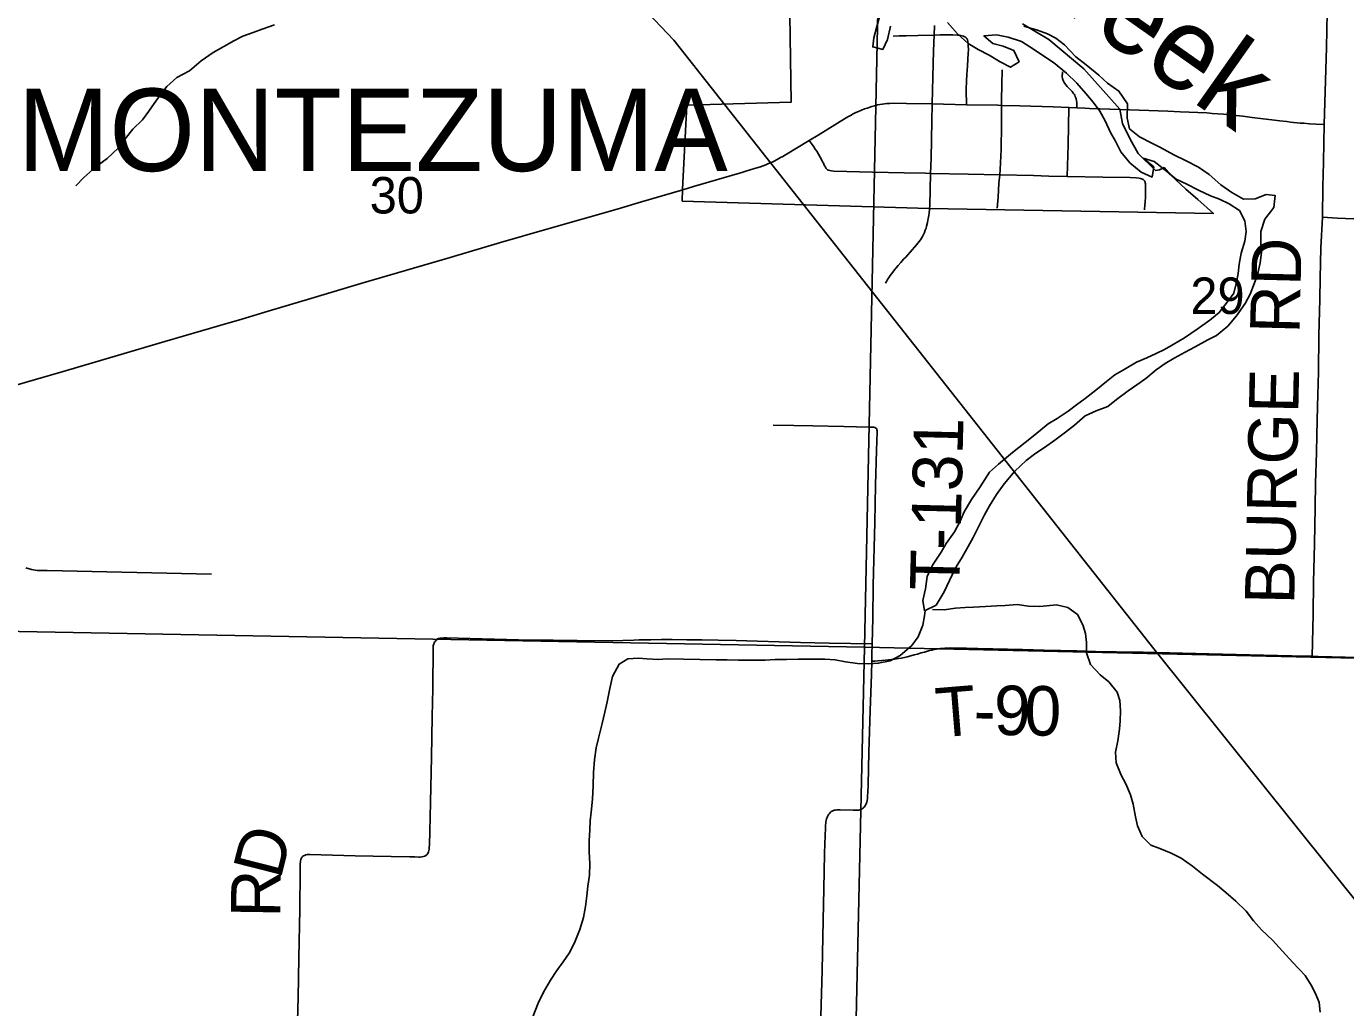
# Model space of a CAD drawing. Extents: x -38.1 to 35.9, y -2.7 to 28.5.
# Drawn here: x 22.099 to 23.615, y 15.586 to 16.713 of the extents above; entities that cross this region are included whole.
import ezdxf

# ---------------------------------------------------------------- set-up
doc = ezdxf.new("R2010")
doc.units = 0
for name, color, linetype in [('GM_X_City_Street', 7, 'Continuous'), ('GM_X_City_Street_Text', 7, 'Continuous'), ('GM_X_Corporation', 7, 'Continuous'), ('GM_X_Interchange_Ramps', 7, 'Continuous'), ('GM_X_Interstate_Shield', 7, 'Continuous'), ('GM_X_Major_River_Text', 7, 'Continuous'), ('GM_X_Minor_Lake', 7, 'Continuous'), ('GM_X_Minor_River', 7, 'Continuous'), ('GM_X_Section', 7, 'Continuous'), ('GM_X_Township_Road_Text', 7, 'Continuous'), ('GM_X_Township_Subdivision', 7, 'Continuous'), ('GM_X_US_Route', 7, 'Continuous')]:
    doc.layers.add(name, color=color, linetype=linetype)

msp = doc.modelspace()

# ---------------------------------------------------------------- linework, layer by layer
at = {"layer": 'GM_X_City_Street'}
for points in [[(23.0952, 16.7014), (23.1018, 16.7016), (23.1101, 16.7017), (23.1234, 16.7021), (23.1421, 16.7025), (23.149, 16.7027), (23.1593, 16.7028), (23.1635, 16.7027), (23.1691, 16.7025), (23.1712, 16.7023), (23.1728, 16.702), (23.1744, 16.7016), (23.1758, 16.7012), (23.1772, 16.7005), (23.1785, 16.6997), (23.1795, 16.6986), (23.1803, 16.6972), (23.1808, 16.6954), (23.1811, 16.693), (23.1813, 16.6904), (23.1814, 16.6862), (23.1813, 16.6814), (23.1809, 16.6751), (23.1803, 16.667), (23.1799, 16.6621), (23.1795, 16.6571), (23.1792, 16.6505), (23.1789, 16.6397), (23.1792, 16.6226)], [(23.2193, 16.6218), (23.2195, 16.6277), (23.22, 16.646), (23.2204, 16.6628)], [(23.3062, 16.619), (23.3062, 16.6229), (23.3061, 16.6252), (23.3058, 16.627), (23.3054, 16.6292), (23.3049, 16.6306), (23.3043, 16.632), (23.3036, 16.6334), (23.3028, 16.6346), (23.3019, 16.636), (23.3007, 16.6376), (23.2991, 16.6394), (23.2969, 16.6417), (23.2951, 16.6435), (23.2934, 16.6454), (23.2922, 16.6469), (23.2914, 16.6482), (23.2906, 16.6498), (23.2899, 16.6517), (23.2895, 16.6529), (23.2893, 16.6543), (23.2892, 16.6556), (23.2892, 16.6569), (23.2894, 16.6582), (23.2897, 16.6602)], [(23.2147, 16.5039), (23.2155, 16.5166), (23.2165, 16.5324), (23.2175, 16.542), (23.2178, 16.5482), (23.219, 16.571), (23.2193, 16.5994), (23.2193, 16.6218)], [(23.2951, 16.54), (23.2959, 16.5768), (23.2967, 16.6193)], [(22.9984, 16.5814), (23.0018, 16.5769), (23.0037, 16.5743), (23.0056, 16.5717), (23.0072, 16.5691), (23.0091, 16.566), (23.0111, 16.5625), (23.0126, 16.5596), (23.014, 16.5569), (23.0148, 16.5554), (23.0154, 16.5543), (23.0163, 16.5526), (23.0173, 16.5508), (23.0182, 16.5494), (23.0194, 16.548), (23.0207, 16.5473), (23.0223, 16.5469), (23.0242, 16.5466), (23.0268, 16.5463), (23.0712, 16.5452), (23.1078, 16.5444), (23.132, 16.5439), (23.138, 16.5437)], [(23.138, 16.5437), (23.1812, 16.543), (23.2175, 16.542), (23.2562, 16.5413), (23.2739, 16.5407), (23.2951, 16.54), (23.3358, 16.5394), (23.3674, 16.5389), (23.3743, 16.5386), (23.3778, 16.5382), (23.3792, 16.5379), (23.3805, 16.5376), (23.3815, 16.5371), (23.3822, 16.5366), (23.3831, 16.536), (23.3837, 16.5353), (23.3842, 16.5345), (23.3845, 16.5338), (23.3847, 16.5329), (23.3849, 16.5318), (23.3849, 16.5307), (23.385, 16.5293), (23.3851, 16.5277), (23.3851, 16.5253), (23.3851, 16.5209), (23.385, 16.5178), (23.3849, 16.5154), (23.3847, 16.5124), (23.3844, 16.51), (23.3843, 16.508), (23.3836, 16.502)]]:
    msp.add_lwpolyline(points, dxfattribs=at)
at = {"layer": 'GM_X_City_Street_Text'}
for points in [[(23.5902, 16.5999), (23.5898, 16.5791), (23.5894, 16.5561), (23.5887, 16.5287), (23.5881, 16.4933)], [(23.5881, 16.4933), (23.6057, 16.4923), (23.6149, 16.4919), (23.6242, 16.4916), (23.659, 16.491), (23.756, 16.489), (23.7901, 16.488), (23.8311, 16.4871), (23.9206, 16.4851), (24.0001, 16.4833), (24.0324, 16.4826), (24.0907, 16.4813)]]:
    msp.add_lwpolyline(points, dxfattribs=at)
at = {"layer": 'GM_X_Corporation'}
msp.add_lwpolyline([(25.4101, 13.4873), (25.0847, 13.9186), (24.5478, 14.5412), (23.9622, 15.2897), (23.3945, 15.9977), (22.8429, 16.6968), (22.7771, 16.7664), (22.2793, 17.0387), (22.174, 17.095), (22.1183, 17.1348), (22.0806, 17.1798), (21.9636, 17.4041), (21.7841, 17.7749), (21.744, 17.8537), (21.7155, 17.9287), (21.6978, 17.9866), (21.6921, 18.0413), (21.6956, 18.1468), (21.7163, 18.7934), (21.7602, 19.7303), (21.7602, 19.7308)], dxfattribs=at)
at = {"layer": 'GM_X_Interchange_Ramps'}
for points in [[(23.5902, 16.5999), (23.5928, 16.6884), (23.5935, 16.7282)], [(23.1399, 16.6235), (23.1411, 16.6695), (23.1415, 16.6844), (23.1421, 16.7025), (23.1424, 16.7135)], [(22.9211, 16.5448), (22.9259, 16.5462), (22.9357, 16.5493), (22.9425, 16.5514), (22.9456, 16.5525), (22.9488, 16.5537), (22.9517, 16.5549), (22.9551, 16.5564), (22.9582, 16.5579), (22.9617, 16.5597), (22.9655, 16.5618), (22.9683, 16.5633), (22.9714, 16.5652), (22.9984, 16.5814), (23.0087, 16.5876), (23.0392, 16.6063), (23.043, 16.6086), (23.0461, 16.6104), (23.049, 16.612), (23.052, 16.6135), (23.0552, 16.6149), (23.0585, 16.6164), (23.0619, 16.6177), (23.0652, 16.6188), (23.0705, 16.6205), (23.0737, 16.6214), (23.0772, 16.6223), (23.0798, 16.6229), (23.0827, 16.6234), (23.0851, 16.6237), (23.0877, 16.624), (23.0912, 16.6241), (23.0953, 16.6242), (23.1102, 16.6239), (23.1399, 16.6235)], [(23.1399, 16.6235), (23.1792, 16.6226), (23.2153, 16.6219)], [(23.2153, 16.6219), (23.2193, 16.6218), (23.2405, 16.6214), (23.2789, 16.62), (23.2967, 16.6193), (23.3062, 16.619), (23.3154, 16.6186)], [(23.3154, 16.6186), (23.3205, 16.6184), (23.3559, 16.617)], [(23.3559, 16.617), (23.4107, 16.6153), (23.4249, 16.6146)], [(23.4249, 16.6146), (23.4554, 16.6132), (23.4614, 16.6127), (23.4681, 16.6121), (23.4745, 16.6116), (23.481, 16.6109), (23.489, 16.6101), (23.4969, 16.6093), (23.5076, 16.6081), (23.5203, 16.6065), (23.53, 16.6054), (23.5393, 16.6042), (23.5475, 16.6032), (23.5514, 16.6027), (23.5551, 16.6023), (23.5592, 16.6019), (23.5627, 16.6016), (23.5667, 16.6013), (23.5734, 16.6008), (23.581, 16.6004), (23.5902, 16.5999)], [(22.8533, 16.525), (22.8657, 16.5286), (22.9211, 16.5448)], [(21.976, 16.2689), (21.9979, 16.2748), (22.022, 16.2818), (22.0591, 16.2924), (22.0859, 16.3002), (22.1098, 16.307), (22.1414, 16.3163), (22.2011, 16.3337), (22.2583, 16.3506), (22.3215, 16.3692), (22.3466, 16.3764), (22.3769, 16.3856), (22.4258, 16.4), (22.4836, 16.4171), (22.5862, 16.4472), (22.644, 16.4643), (22.6972, 16.4795), (22.7778, 16.5028), (22.8058, 16.5111), (22.8533, 16.525)]]:
    msp.add_lwpolyline(points, dxfattribs=at)
at = {"layer": 'GM_X_Interstate_Shield'}
for points in [[(23.0797, 16.7245), (23.0763, 16.7124), (23.073, 16.6996), (23.0716, 16.689), (23.083, 16.6861), (23.0885, 16.6974), (23.0919, 16.7129)], [(23.2959, 16.2708), (23.2836, 16.2624), (23.2732, 16.2562), (23.2577, 16.2436), (23.2465, 16.2348), (23.2322, 16.2233), (23.2159, 16.2096), (23.2058, 16.2004), (23.1948, 16.1839), (23.185, 16.1693), (23.1767, 16.1551), (23.1719, 16.1442), (23.1656, 16.1322), (23.1561, 16.1187), (23.1502, 16.1086), (23.1404, 16.0936), (23.134, 16.0809), (23.1322, 16.0665), (23.1292, 16.0533), (23.1312, 16.0414), (23.1443, 16.048), (23.1538, 16.063), (23.1597, 16.0761), (23.1673, 16.0919), (23.1744, 16.1031), (23.1811, 16.1151), (23.1871, 16.1256), (23.1922, 16.1361), (23.1998, 16.1515), (23.2057, 16.162), (23.2136, 16.1751), (23.2226, 16.1871), (23.2347, 16.2016), (23.2479, 16.2138), (23.2588, 16.2223), (23.2688, 16.2289), (23.2807, 16.2374), (23.2931, 16.2466), (23.3032, 16.2547), (23.3156, 16.2651), (23.3282, 16.2709), (23.3416, 16.2759), (23.3517, 16.284), (23.3652, 16.294), (23.3749, 16.3009), (23.3853, 16.3083), (23.3973, 16.3183), (23.4077, 16.3253), (23.4177, 16.3315), (23.4304, 16.3384), (23.4419, 16.3446), (23.4566, 16.3526), (23.4666, 16.3577), (23.4797, 16.3684), (23.4895, 16.38), (23.4993, 16.3942), (23.5052, 16.405), (23.5109, 16.4201), (23.5145, 16.4307), (23.5167, 16.4409), (23.5181, 16.453), (23.5176, 16.4636), (23.5175, 16.4769), (23.522, 16.4912), (23.5325, 16.5047), (23.534, 16.5183), (23.5237, 16.5193), (23.5111, 16.5146), (23.4974, 16.5142), (23.4843, 16.5217), (23.4716, 16.5307), (23.4582, 16.5424), (23.4458, 16.5507), (23.4308, 16.5586), (23.4176, 16.565), (23.4022, 16.5733), (23.3921, 16.5785), (23.3782, 16.5856), (23.3666, 16.595), (23.3639, 16.6072), (23.3642, 16.6235), (23.3543, 16.6382), (23.3412, 16.6472), (23.3312, 16.6566), (23.3166, 16.6683), (23.305, 16.6777), (23.292, 16.6912), (23.282, 16.6991), (23.2722, 16.7042), (23.2609, 16.7083), (23.245, 16.7128)], [(23.1574, 16.7171), (23.1689, 16.7039), (23.1811, 16.693), (23.1928, 16.6859), (23.2055, 16.6795), (23.2179, 16.672), (23.2299, 16.6657), (23.2396, 16.6719), (23.2338, 16.685), (23.2213, 16.6898), (23.2096, 16.6931), (23.1992, 16.7017), (23.2137, 16.7029), (23.2273, 16.7003), (23.2424, 16.6954), (23.2562, 16.6864), (23.2693, 16.6777), (23.2794, 16.671), (23.294, 16.6589), (23.3059, 16.6473), (23.3163, 16.6356), (23.3248, 16.6256), (23.3325, 16.6151), (23.3387, 16.604), (23.3449, 16.5906), (23.3504, 16.5806), (23.3565, 16.5683), (23.3669, 16.5559), (23.38, 16.5453), (23.3924, 16.5394), (23.3945, 16.5511), (23.3822, 16.5612), (23.3947, 16.5575), (23.407, 16.5478), (23.42, 16.5372), (23.4324, 16.5312), (23.446, 16.5245), (23.4595, 16.5181), (23.4701, 16.5141), (23.481, 16.5089), (23.4929, 16.501), (23.4991, 16.4891), (23.5004, 16.4769), (23.499, 16.4659), (23.4949, 16.452), (23.4927, 16.4395), (23.4913, 16.4289), (23.4896, 16.4187), (23.4863, 16.4062), (23.4788, 16.3958), (23.4694, 16.3838), (23.459, 16.375), (23.4443, 16.3647), (23.4296, 16.3548), (23.4169, 16.3471), (23.4069, 16.3416), (23.3973, 16.3369), (23.3866, 16.3318), (23.3747, 16.3268), (23.3604, 16.3184), (23.3497, 16.3122), (23.34, 16.3048), (23.328, 16.2948), (23.3156, 16.2852), (23.3056, 16.2778), (23.2959, 16.2708)]]:
    msp.add_lwpolyline(points, dxfattribs=at)
at = {"layer": 'GM_X_Major_River_Text'}
for points in [[(23.138, 16.5437), (23.1386, 16.5614), (23.1395, 16.6039), (23.1399, 16.6235)], [(23.1368, 16.5029), (23.1371, 16.5068), (23.1374, 16.5247), (23.138, 16.5437)], [(23.0863, 16.4178), (23.0874, 16.4197), (23.0882, 16.4212), (23.0892, 16.4229), (23.0905, 16.4247), (23.0916, 16.4264), (23.0931, 16.4285), (23.0945, 16.4302), (23.0965, 16.4328), (23.0984, 16.4352), (23.1007, 16.438), (23.1038, 16.4415), (23.107, 16.4451), (23.1094, 16.4476), (23.1117, 16.4501), (23.1145, 16.4531), (23.117, 16.456), (23.1195, 16.4589), (23.1219, 16.4617), (23.1235, 16.4636), (23.125, 16.4656), (23.1264, 16.4675), (23.1275, 16.4693), (23.1287, 16.4712), (23.1297, 16.4734), (23.1309, 16.4758), (23.1319, 16.4784), (23.1328, 16.4809), (23.1334, 16.4832), (23.1345, 16.4874), (23.1354, 16.492), (23.136, 16.4955), (23.1363, 16.4983), (23.1367, 16.5017), (23.1368, 16.5029)], [(23.5766, 15.9891), (23.5774, 16.0372), (23.578, 16.0742), (23.5791, 16.1183), (23.5799, 16.1599), (23.5804, 16.1879), (23.5813, 16.2233), (23.5819, 16.2432), (23.5825, 16.2761), (23.5836, 16.3159), (23.5842, 16.3575), (23.5852, 16.3991), (23.5857, 16.4234), (23.5865, 16.4581), (23.5881, 16.4933)], [(22.957, 16.2546), (22.9809, 16.2542), (23.0028, 16.2539), (23.0382, 16.253), (23.0673, 16.2523), (23.071, 16.2523), (23.0728, 16.2522), (23.0741, 16.2518), (23.075, 16.2513), (23.0757, 16.2507)], [(23.0708, 16.0035), (23.0715, 16.0328), (23.0721, 16.0708), (23.0738, 16.1428), (23.0746, 16.1857), (23.0759, 16.2255), (23.0766, 16.2469), (23.0765, 16.2482), (23.0764, 16.2491), (23.0761, 16.25), (23.0757, 16.2507)], [(22.0986, 16.0907), (22.105, 16.0887), (22.1114, 16.0877), (22.123, 16.0875), (22.3117, 16.0836)], [(22.4105, 15.5699), (22.4113, 15.5973), (22.4122, 15.6429), (22.4133, 15.6986), (22.4139, 15.7415), (22.4138, 15.7489), (22.4138, 15.7511), (22.414, 15.7529), (22.4141, 15.7543), (22.4145, 15.7556), (22.4148, 15.7564), (22.4153, 15.7575), (22.4159, 15.7585), (22.4166, 15.7593), (22.4174, 15.7599), (22.4187, 15.7605), (22.4201, 15.761), (22.4218, 15.7613), (22.4232, 15.7614), (22.4251, 15.7614), (22.438, 15.7611), (22.4769, 15.7601), (22.5183, 15.7591), (22.5398, 15.7588), (22.5455, 15.7586), (22.5499, 15.7585), (22.5517, 15.7585), (22.5535, 15.7586), (22.5554, 15.759), (22.5571, 15.7596), (22.5586, 15.7606), (22.5595, 15.7614), (22.5601, 15.7624), (22.5607, 15.7633), (22.5612, 15.7647), (22.5616, 15.7662), (22.5619, 15.7677), (22.562, 15.7699), (22.5623, 15.7727), (22.5627, 15.7883), (22.5631, 15.8044), (22.5646, 15.8731), (22.5655, 15.92), (22.5661, 15.9523), (22.5662, 15.9629), (22.5663, 15.9685), (22.5664, 15.9827), (22.5664, 15.9944), (22.5664, 15.9965), (22.5665, 15.9992), (22.5667, 16.001), (22.567, 16.0022), (22.5673, 16.0033), (22.5677, 16.0043), (22.5681, 16.0052), (22.5687, 16.006), (22.5695, 16.0071), (22.5703, 16.0078), (22.5709, 16.0085), (22.5717, 16.0091), (22.5725, 16.0094), (22.5733, 16.0097), (22.5745, 16.0099), (22.5763, 16.0101), (22.5786, 16.0102), (22.5823, 16.0103), (22.5952, 16.0099), (22.6647, 16.0082), (22.7044, 16.0075), (22.72, 16.0073)], [(22.72, 16.0073), (22.7318, 16.0071), (22.7726, 16.007), (22.7843, 16.0073), (22.7969, 16.0078), (22.8033, 16.008), (22.81, 16.0082), (22.8167, 16.0082), (22.8287, 16.0083), (22.8411, 16.0084), (22.8579, 16.0082), (22.8753, 16.008), (22.8941, 16.0076), (22.9148, 16.0071), (22.9884, 16.0051), (23.0214, 16.0043), (23.0708, 16.0035)], [(23.0704, 15.9834), (23.0705, 15.9912), (23.0708, 16.0035)], [(23.0704, 15.9834), (23.0741, 15.9835), (23.0774, 15.9837), (23.082, 15.9841), (23.0861, 15.9845), (23.0896, 15.985), (23.0933, 15.9855), (23.097, 15.9859), (23.1008, 15.9865), (23.1043, 15.9871), (23.1081, 15.9878), (23.1112, 15.9886), (23.1152, 15.9896), (23.119, 15.9906), (23.1231, 15.9917), (23.1273, 15.993), (23.131, 15.994), (23.1343, 15.9949), (23.1369, 15.9956), (23.1393, 15.9962), (23.142, 15.9968), (23.1448, 15.9973), (23.1469, 15.9976), (23.1492, 15.9979), (23.1515, 15.9982), (23.1542, 15.9984), (23.1579, 15.9986), (23.1608, 15.9987), (23.1668, 15.9986), (23.1792, 15.9983), (23.1924, 15.9979), (23.2438, 15.9969), (23.2686, 15.9963), (23.3059, 15.9953), (23.3273, 15.9948), (23.3514, 15.9944), (23.3824, 15.9937), (23.4578, 15.9919), (23.5204, 15.9904), (23.5532, 15.9897), (23.5766, 15.9891)], [(23.0113, 15.5492), (23.0134, 15.6281), (23.0147, 15.6859), (23.0154, 15.7219), (23.0163, 15.7622), (23.0167, 15.7739), (23.0171, 15.7922), (23.0174, 15.7953), (23.0175, 15.7973), (23.0178, 15.7989), (23.0181, 15.8005), (23.0186, 15.8023), (23.0191, 15.8038), (23.0196, 15.8051), (23.0203, 15.8065), (23.0211, 15.8078), (23.0221, 15.8089), (23.023, 15.81), (23.0239, 15.8107), (23.0248, 15.8112), (23.0259, 15.8117), (23.0272, 15.8122), (23.0288, 15.8125), (23.0304, 15.8127), (23.0322, 15.8129), (23.0341, 15.8129), (23.0491, 15.8122), (23.0509, 15.8122), (23.0524, 15.8122), (23.0542, 15.8123), (23.0556, 15.8125), (23.0568, 15.8128), (23.058, 15.8132), (23.059, 15.8137), (23.0599, 15.8144), (23.0608, 15.8151), (23.0617, 15.816), (23.0625, 15.8169), (23.0632, 15.818), (23.0641, 15.8198), (23.0647, 15.8215), (23.0651, 15.8234), (23.0654, 15.8258), (23.0657, 15.8284), (23.066, 15.833), (23.0662, 15.8415), (23.0672, 15.8788), (23.0687, 15.9268), (23.0702, 15.9682), (23.0704, 15.9834)], [(23.5766, 15.9891), (23.5833, 15.9889), (23.6458, 15.9874), (23.6992, 15.9864), (23.7451, 15.9853), (23.7819, 15.9845), (23.811, 15.9839), (23.8685, 15.9826), (23.9179, 15.9815), (23.9626, 15.9803), (24.0198, 15.9792), (24.0844, 15.9779), (24.1173, 15.9771), (24.1689, 15.976), (24.213, 15.9748), (24.2547, 15.9739), (24.2938, 15.973), (24.31, 15.9726), (24.3281, 15.9722)]]:
    msp.add_lwpolyline(points, dxfattribs=at)
at = {"layer": 'GM_X_Section'}
for points in [[(22.3842, 16.7145), (22.37, 16.7095), (22.3596, 16.7056), (22.3478, 16.7013), (22.3374, 16.6958), (22.3259, 16.6896), (22.3139, 16.6827), (22.3, 16.6731), (22.2865, 16.6616), (22.2722, 16.654), (22.2606, 16.6436), (22.2485, 16.6279), (22.2398, 16.6152), (22.2324, 16.6051), (22.2215, 16.5947), (22.2125, 16.5835), (22.2047, 16.5727), (22.1919, 16.5608), (22.1788, 16.5513), (22.1652, 16.539), (22.1559, 16.5294)], [(23.1317, 16.0417), (23.1311, 16.0357), (23.1293, 16.0248), (23.1237, 16.0116), (23.1163, 16.0015), (23.1031, 15.9901), (23.0916, 15.9839), (23.0778, 15.9811), (23.0672, 15.9806), (23.0539, 15.9809), (23.0403, 15.9827), (23.0285, 15.9849), (23.0164, 15.9859), (22.986, 15.9859), (22.9723, 15.9854), (22.9594, 15.9853), (22.948, 15.9848), (22.9336, 15.9847), (22.9172, 15.9847), (22.9043, 15.985), (22.8918, 15.9849), (22.8352, 15.9862), (22.8253, 15.9856), (22.812, 15.9863), (22.8025, 15.9869), (22.79, 15.9861), (22.7803, 15.9802), (22.7724, 15.9659), (22.7695, 15.9523), (22.7665, 15.9368), (22.7639, 15.9251), (22.7606, 15.9119), (22.7564, 15.8949), (22.7539, 15.884), (22.7517, 15.87), (22.7506, 15.8556), (22.7503, 15.8408), (22.7495, 15.8252), (22.748, 15.81), (22.7471, 15.8002), (22.7465, 15.7896), (22.7458, 15.7771), (22.7459, 15.7645), (22.7464, 15.7512), (22.746, 15.7376), (22.7442, 15.7251), (22.7429, 15.7141), (22.7414, 15.7016), (22.7393, 15.6891), (22.7352, 15.6752), (22.7291, 15.6601), (22.7228, 15.6481), (22.7157, 15.638), (22.7087, 15.6283), (22.7012, 15.6171), (22.6933, 15.6032), (22.6873, 15.5908), (22.6801, 15.5731)], [(23.1404, 16.0428), (23.1537, 16.0425), (23.1666, 16.0444), (23.1777, 16.0453), (23.1872, 16.0455), (23.2012, 16.0463), (23.2142, 16.0472), (23.2237, 16.0473), (23.2374, 16.0485), (23.2506, 16.0467), (23.2636, 16.0464), (23.2826, 16.0483), (23.2958, 16.0453), (23.3067, 16.0371), (23.3128, 16.0252), (23.316, 16.0152), (23.317, 16.005), (23.3171, 15.9932), (23.3217, 15.9798), (23.3328, 15.9678), (23.3429, 15.9596), (23.3522, 15.948), (23.3554, 15.9384), (23.3562, 15.9266), (23.356, 15.9149), (23.355, 15.9054), (23.3532, 15.8921), (23.3506, 15.8789), (23.3511, 15.8667), (23.3569, 15.8526), (23.3623, 15.8426), (23.3677, 15.8299), (23.3709, 15.8192), (23.3736, 15.8047), (23.3757, 15.7944), (23.3811, 15.7821), (23.3911, 15.772), (23.4013, 15.7684), (23.4145, 15.7628), (23.4261, 15.7572), (23.4389, 15.7482), (23.4504, 15.7388), (23.4676, 15.7259), (23.4773, 15.7177), (23.4889, 15.7079), (23.5004, 15.6963), (23.5089, 15.6851), (23.5181, 15.675), (23.5308, 15.6629), (23.5423, 15.6505), (23.5541, 15.6373), (23.5683, 15.6226), (23.5752, 15.6114), (23.5803, 15.6018), (23.5843, 15.5915), (23.5855, 15.5804)]]:
    msp.add_lwpolyline(points, dxfattribs=at)
at = {"layer": 'GM_X_US_Route'}
for points in [[(21.9892, 17.0222), (23.083, 17.004), (23.0619, 15.9996), (21.9663, 16.0198)], [(23.083, 17.004), (24.0999, 16.9841), (24.0707, 15.9769), (23.0619, 15.9996)], [(21.9663, 16.0198), (23.0619, 15.9996), (23.0396, 14.9923), (21.9409, 15.0133)], [(23.0619, 15.9996), (24.0707, 15.9769), (24.0515, 14.9714), (23.0396, 14.9923)]]:
    msp.add_lwpolyline(points, close=True, dxfattribs=at)
msp.add_lwpolyline([(23.2435, 16.7156), (23.2738, 16.6977), (23.314, 16.6638), (23.3556, 16.6175), (23.3586, 16.6011), (23.3673, 16.583), (23.3765, 16.5665), (23.3965, 16.5471), (23.4012, 16.5478), (23.4062, 16.5504), (23.4135, 16.542), (23.4311, 16.5255), (23.4452, 16.5137), (23.463, 16.4976), (23.1365, 16.5034), (22.8527, 16.512), (22.8531, 16.5255), (22.858, 16.6219), (22.9778, 16.6255), (22.974, 16.8762)], dxfattribs=at)

# ---------------------------------------------------------------- texts
at = {"layer": 'GM_X_Minor_Lake'}
for s, height, rotation, p in [('RD', 0.05682, 88.5177, (23.5617, 16.3593)), ('BURGE', 0.05682, 88.7836, (23.5558, 16.0484)), ('T-131', 0.05682, 88.5961, (23.171, 16.0643)), ('T', 0.0568, 4.7281, (23.1462, 15.8957)), ('9', 0.0568, 359.2537, (23.2105, 15.8988)), ('0', 0.0568, 359.296, (23.2456, 15.8983)), ('-', 0.0568, 359.1569, (23.1871, 15.8991)), ('D', 0.0568, 75.7579, (22.3911, 15.7319)), ('R', 0.0568, 89.1432, (22.3908, 15.6887))]:
    msp.add_text(s, height=height, rotation=rotation, dxfattribs=at).set_placement(p)
at = {"layer": 'GM_X_Minor_River'}
for s, p in [('30', (22.4936, 16.4977)), ('29', (23.4365, 16.3823))]:
    msp.add_text(s, height=0.04186, rotation=0, dxfattribs=at).set_placement(p)
at = {"layer": 'GM_X_Township_Road_Text'}
msp.add_text('Creek', height=0.09468, rotation=324.8182, dxfattribs=at).set_placement((23.2126, 16.7853))
at = {"layer": 'GM_X_Township_Subdivision'}
msp.add_text('MONTEZUMA', height=0.0947, rotation=0, dxfattribs=at).set_placement((22.089, 16.5464))

doc.saveas('drawing.dxf')
